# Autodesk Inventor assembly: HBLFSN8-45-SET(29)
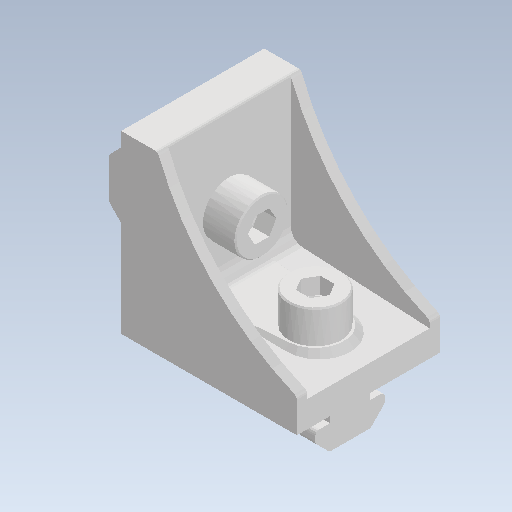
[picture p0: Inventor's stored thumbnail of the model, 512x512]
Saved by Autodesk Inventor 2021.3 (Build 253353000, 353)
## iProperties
Created: 2022-02
Part Number: HBLFSN8-45-SET(29)
Document SubType Name: Assembly
Designer: kengo
Author: kengo
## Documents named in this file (4)
- C:\Users\kengo\Documents\S2S_frame\SDC345\frame_misumi_ver12\HBLFSN8-45-SET(29).iam
- C:\Users\kengo\Documents\S2S_frame\SDC345\frame_misumi_ver12\HBLFSN8-45.ipt
- C:\Users\kengo\Documents\S2S_frame\SDC345\frame_misumi_ver12\HNTT8-8.ipt
- C:\Users\kengo\Documents\S2S_frame\SDC345\frame_misumi_ver12\CBM8-20.ipt
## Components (5 placed, 3 different names)
1. HBLFSN8-45
2. HNTT8-8
3. CBM8-20
4. HNTT8-8:1
5. CBM8-20:1
